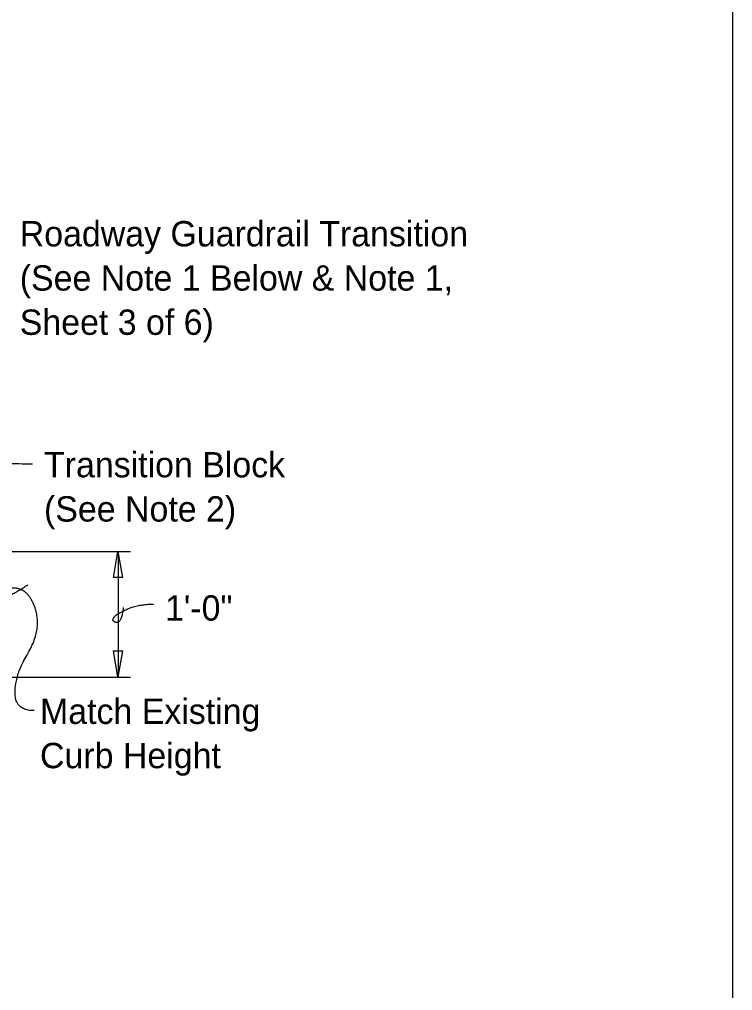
# Model space of a CAD drawing. Extents: x 1.5 to 68.7, y 0 to 31.
# Drawn here: x 36.86 to 42.53, y 9.19 to 16.91 of the extents above; entities that cross this region are included whole.
import ezdxf

# ---------------------------------------------------------------- set-up
doc = ezdxf.new("R2010")
doc.units = 0
for name, color, linetype in [('ActivePts-ConstElements', 7, 'Continuous'), ('Dimension', 7, 'Continuous'), ('TextStructures', 7, 'Continuous')]:
    doc.layers.add(name, color=color, linetype=linetype)

# ---------------------------------------------------------------- blocks, each defined once
blk = doc.blocks.new('Terminator-Arrow')
at = {"layer": 'Dimension'}
blk.add_lwpolyline([(0, 0), (-0.00041, 0.000069), (-0.00041, -0.000069)], close=True, dxfattribs=at)

msp = doc.modelspace()

# ---------------------------------------------------------------- linework, layer by layer
at = {"layer": 'ActivePts-ConstElements'}
msp.add_lwpolyline([(1.4667, 28.1828), (42.5333, 28.1828), (42.5333, 1.7828), (1.4667, 1.7828)], close=True, dxfattribs=at)
at = {"layer": 'Dimension'}
for p, q in [((34.7705, 12.682), (37.7448, 12.682)), ((37.6451, 12.6821), (37.6451, 11.6821)), ((34.7705, 11.682), (37.7448, 11.682))]:
    msp.add_line(p, q, dxfattribs=at)
for points in [[(36.9638, 13.3766), (36.3023, 13.3835), (36.0282, 13.2463), (35.8452, 13.0751), (35.6496, 12.7777), (35.6496, 12.4881), (35.1021, 12.2847), (34.6328, 12.2768)], [(36.9767, 11.4144), (36.8259, 11.4144), (36.8259, 11.6957), (37.0041, 11.9975), (37.0041, 12.217), (36.9013, 12.3885), (36.7299, 12.3885), (36.6545, 12.3062), (36.7573, 12.3062), (36.9287, 12.416)], [(37.6866, 12.2346), (37.6705, 12.0931), (37.5692, 12.1451), (37.7866, 12.2625), (37.9279, 12.2625)]]:
    msp.add_open_spline(points, degree=2, dxfattribs=at)

# ---------------------------------------------------------------- block references
at = {"layer": 'Dimension', "xscale": 506.349, "yscale": -512.1577380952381}
for p, rotation in [((37.6445, 12.6818), 90), ((37.6445, 11.6817), -90)]:
    msp.add_blockref('Terminator-Arrow', p, dxfattribs=dict(at, rotation=rotation))

# ---------------------------------------------------------------- texts
at = {"layer": 'Dimension'}
for s, p in [('Roadway Guardrail Transition', (36.8631, 15.1086)), ('(See Note 1 Below & Note 1,', (36.8631, 14.7566)), ('Sheet 3 of 6)', (36.8631, 14.4046)), ('Transition Block', (37.0561, 13.2708)), ('(See Note 2)', (37.0561, 12.9188)), ('Match Existing ', (37.0243, 11.3085)), ('Curb Height', (37.0243, 10.9565))]:
    msp.add_text(s, height=0.2016, dxfattribs=at).set_placement(p)
at = {"layer": 'TextStructures'}
msp.add_text('1\'-0"', height=0.2016, dxfattribs=at).set_placement((38.0185, 12.1308))

doc.saveas('drawing.dxf')
